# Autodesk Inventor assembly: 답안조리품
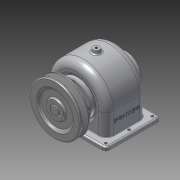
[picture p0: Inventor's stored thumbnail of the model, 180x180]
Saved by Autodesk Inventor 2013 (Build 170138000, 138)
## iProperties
Created: 2015-09
Part Number: 답안조리품
Document SubType Name: Assembly
Designer: Administrator
Author: Administrator
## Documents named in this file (14)
- C:\Users\Administrator\Desktop\450908V1021\답안조리품.iam
- C:\Users\Administrator\Desktop\450908V1021\본체.ipt
- C:\Users\Administrator\Desktop\450908V1021\V-벨트풀리.ipt
- C:\Users\Administrator\Desktop\450908V1021\뒤커버.ipt
- C:\Users\Administrator\Desktop\450908V1021\멈춤나사 - M4x10.ipt
- C:\Users\Administrator\Desktop\450908V1021\베어링 6203.ipt
- C:\Users\Administrator\Desktop\450908V1021\볼트 M3 x 8.ipt
- C:\Users\Administrator\Desktop\450908V1021\볼트 M3 x 10.ipt
- C:\Users\Administrator\Desktop\450908V1021\스퍼기어.ipt
- C:\Users\Administrator\Desktop\450908V1021\앞커버.ipt
- C:\Users\Administrator\Desktop\450908V1021\오일 실 17 32 8.ipt
- C:\Users\Administrator\Desktop\450908V1021\축.ipt
- C:\Users\Administrator\Desktop\450908V1021\키 - 5 x 5 x 18.ipt
- C:\Users\Administrator\Desktop\450908V1021\키 - 6 x 6 x 22.ipt
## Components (9 placed, 3 different names)
1. V-벨트풀리:1 — 각도:3
2. ISO 4762 M3 x 8:1
3. ISO 4762 M3 x 8:2
4. ISO 4762 M3 x 8:3
5. ISO 4762 M3 x 8:4
6. ISO 4762 M3 x 10:1
7. ISO 4762 M3 x 10:2
8. ISO 4762 M3 x 10:3
9. ISO 4762 M3 x 10:4
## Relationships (1: Angle 1)
- 각도:3 [Angle]: V-벨트풀리:1
